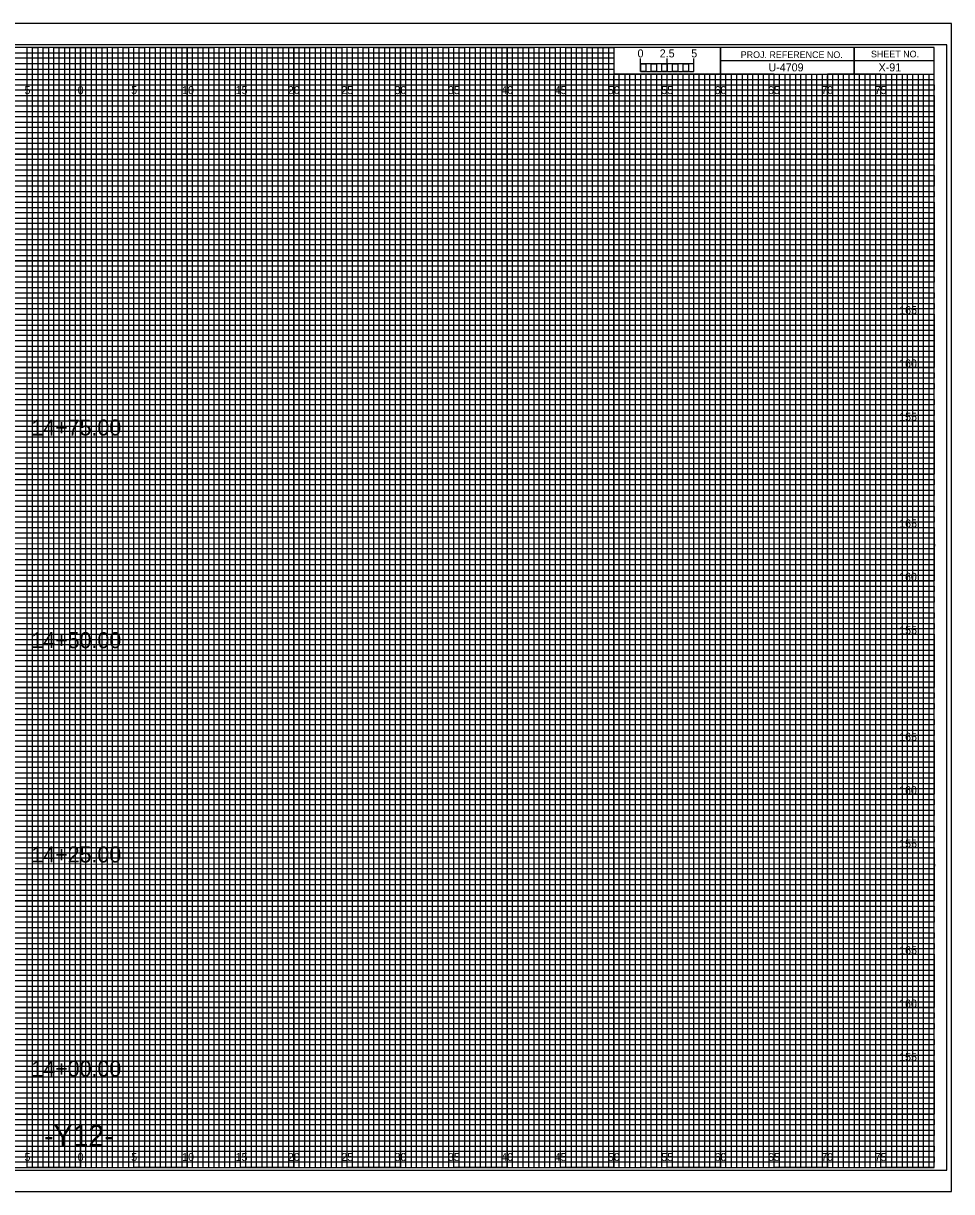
# Model space of a CAD drawing. Extents: x -7 to 162, y 328 to 437.
# Drawn here: x 74.6 to 161.7, y 327.7 to 437.2 of the extents above; entities that cross this region are included whole.
import ezdxf

# ---------------------------------------------------------------- set-up
doc = ezdxf.new("R2010")
doc.units = 0
for name, color, linetype in [('Exist Cross Section Cell', 7, 'Continuous'), ('Exist XS Center Line Elevation Label', 7, 'Continuous'), ('Exist XS Ground Line', 7, 'Continuous'), ('Prop CMT Conc Surface', 7, 'Continuous'), ('Prop CMT Concrete Structures', 7, 'Continuous'), ('Prop CMT Pvmt Course 1', 7, 'Continuous'), ('Prop CMT Pvmt Course 1 CG', 7, 'Continuous'), ('Prop CMT Pvmt Course 2', 7, 'Continuous'), ('Prop CMT Pvmt Course 3', 7, 'Continuous'), ('Prop CMT Pvmt Surface', 7, 'Continuous'), ('Prop CMT Slope Grass', 7, 'Continuous'), ('Prop CMT Subgrade Earthwork', 7, 'Continuous'), ('Prop XS Finish Grade CurbGutter', 7, 'Continuous'), ('Prop XS Hydro Elevations', 7, 'Continuous'), ('Prop XS SE Text', 7, 'Continuous'), ('Prop XS Side Slope Text', 7, 'Continuous'), ('Scratch_Level_0', 7, 'Continuous')]:
    doc.layers.add(name, color=color, linetype=linetype)

msp = doc.modelspace()

# ---------------------------------------------------------------- linework, layer by layer
at = {"layer": 'Exist XS Center Line Elevation Label'}
for points in [[(72.5, 330), (77.5, 330), (77.5, 435), (82.5, 435), (82.5, 330), (87.5, 330), (87.5, 435), (92.5, 435), (92.5, 330), (97.5, 330), (97.5, 435), (102.5, 435), (102.5, 330), (107.5, 330), (107.5, 435), (112.5, 435), (112.5, 330), (117.5, 330), (117.5, 435), (122.5, 435), (122.5, 330), (127.5, 330), (127.5, 435), (129.97, 435), (130, 435), (130, 432.5), (132.5, 432.5), (132.5, 330), (137.5, 330), (137.5, 432.5), (142.5, 432.5), (142.5, 330), (147.5, 330), (147.5, 432.5), (152.5, 432.5), (152.5, 330), (157.5, 330), (157.5, 432.5)], [(0, 432.5), (137.5, 432.5)], [(0, 422.5), (160, 422.5), (160, 427.5), (0, 427.5)], [(0, 412.5), (160, 412.5), (160, 417.5), (0, 417.5)], [(0, 402.5), (160, 402.5), (160, 407.5), (0, 407.5)], [(0, 392.5), (160, 392.5), (160, 397.5), (0, 397.5)], [(0, 382.5), (160, 382.5), (160, 387.5), (0, 387.5)], [(0, 372.5), (160, 372.5), (160, 377.5), (0, 377.5)], [(0, 362.5), (160, 362.5), (160, 367.5), (0, 367.5)], [(0, 352.5), (160, 352.5), (160, 357.5), (0, 357.5)], [(0, 342.5), (160, 342.5), (160, 347.5), (0, 347.5)], [(0, 332.5), (160, 332.5), (160, 337.5), (0, 337.5)]]:
    msp.add_lwpolyline(points, dxfattribs=at)
at = {"layer": 'Exist XS Ground Line'}
for p, q in [((75, 435), (70, 435)), ((75, 330), (75, 435)), ((85, 435), (80, 435)), ((80, 435), (80, 330)), ((85, 330), (85, 435)), ((95, 435), (90, 435)), ((90, 435), (90, 330)), ((95, 330), (95, 435)), ((105, 435), (100, 435)), ((100, 435), (100, 330)), ((105, 330), (105, 435)), ((115, 435), (110, 435)), ((110, 435), (110, 330)), ((115, 330), (115, 435)), ((125, 435), (120, 435)), ((120, 435), (120, 330)), ((125, 330), (125, 435)), ((130, 435), (130, 330)), ((135, 330), (135, 432.5)), ((145, 432.5), (140, 432.5)), ((140, 432.5), (140, 330)), ((145, 330), (145, 432.5)), ((155, 432.5), (150, 432.5)), ((150, 432.5), (150, 330)), ((155, 330), (155, 432.5)), ((80, 330), (75, 330)), ((90, 330), (85, 330)), ((100, 330), (95, 330)), ((110, 330), (105, 330)), ((120, 330), (115, 330)), ((130, 330), (125, 330)), ((140, 330), (135, 330)), ((150, 330), (145, 330)), ((160, 330), (155, 330)), ((160, 330), (160, 330))]:
    msp.add_line(p, q, dxfattribs=at)
for points in [[(0, 430), (160, 430), (160, 425), (0, 425)], [(0, 420), (160, 420), (160, 415), (0, 415)], [(0, 410), (160, 410), (160, 405), (0, 405)], [(0, 400), (160, 400), (160, 395), (0, 395)], [(0, 390), (160, 390), (160, 385), (0, 385)], [(0, 380), (160, 380), (160, 375), (0, 375)], [(0, 370), (160, 370), (160, 365), (0, 365)], [(0, 360), (160, 360), (160, 355), (0, 355)], [(0, 350), (160, 350), (160, 345), (0, 345)], [(0, 340), (160, 340), (160, 335), (0, 335)]]:
    msp.add_lwpolyline(points, dxfattribs=at)
at = {"layer": 'Prop CMT Conc Surface'}
for p, q in [((75, 330), (75, 435)), ((80, 330), (80, 435)), ((85, 330), (85, 435)), ((90, 330), (90, 435)), ((95, 330), (95, 435)), ((100, 330), (100, 435)), ((105, 330), (105, 435)), ((110, 330), (110, 435)), ((115, 330), (115, 435)), ((120, 330), (120, 435)), ((125, 330), (125, 435)), ((130, 330), (130, 432.34)), ((135, 330), (135, 432.34)), ((140, 330), (140, 432.34)), ((145, 330), (145, 432.34)), ((150, 330), (150, 432.34)), ((155, 330), (155, 432.34)), ((0, 430), (160, 430)), ((0, 425), (160, 425)), ((0, 420), (160, 420)), ((0, 415), (160, 415)), ((0, 410), (160, 410)), ((0, 405), (160, 405)), ((0, 400), (160, 400)), ((0, 395), (160, 395)), ((0, 390), (160, 390)), ((0, 385), (160, 385)), ((0, 380), (160, 380)), ((0, 375), (160, 375)), ((0, 370), (160, 370)), ((0, 365), (160, 365)), ((0, 360), (160, 360)), ((0, 355), (160, 355)), ((0, 350), (160, 350)), ((0, 345), (160, 345)), ((0, 340), (160, 340)), ((0, 335), (160, 335))]:
    msp.add_line(p, q, dxfattribs=at)
at = {"layer": 'Prop CMT Pvmt Course 1'}
for p, q in [((133.5, 432.5), (133, 432.5)), ((133, 432.5), (133, 330)), ((133.5, 330), (133.5, 432.5)), ((134.5, 432.5), (134, 432.5)), ((134, 432.5), (134, 330)), ((134.5, 330), (134.5, 432.5)), ((133, 330), (132.5, 330)), ((134, 330), (133.5, 330))]:
    msp.add_line(p, q, dxfattribs=at)
for points in [[(75, 330), (75.5, 330), (75.5, 435), (76, 435), (76, 330)], [(76, 330), (76.5, 330), (76.5, 435), (77, 435), (77, 330)], [(77.5, 330), (78, 330), (78, 435), (78.5, 435), (78.5, 330)], [(78.5, 330), (79, 330), (79, 435), (79.5, 435), (79.5, 330)], [(80, 330), (80.5, 330), (80.5, 435), (81, 435), (81, 330)], [(81, 330), (81.5, 330), (81.5, 435), (82, 435), (82, 330)], [(82.5, 330), (83, 330), (83, 435), (83.5, 435), (83.5, 330)], [(83.5, 330), (84, 330), (84, 435), (84.5, 435), (84.5, 330)], [(85, 330), (85.5, 330), (85.5, 435), (86, 435), (86, 330)], [(86, 330), (86.5, 330), (86.5, 435), (87, 435), (87, 330)], [(87.5, 330), (88, 330), (88, 435), (88.5, 435), (88.5, 330)], [(88.5, 330), (89, 330), (89, 435), (89.5, 435), (89.5, 330)], [(90, 330), (90.5, 330), (90.5, 435), (91, 435), (91, 330)], [(91, 330), (91.5, 330), (91.5, 435), (92, 435), (92, 330)], [(92.5, 330), (93, 330), (93, 435), (93.5, 435), (93.5, 330)], [(93.5, 330), (94, 330), (94, 435), (94.5, 435), (94.5, 330)], [(95, 330), (95.5, 330), (95.5, 435), (96, 435), (96, 330)], [(96, 330), (96.5, 330), (96.5, 435), (97, 435), (97, 330)], [(97.5, 330), (98, 330), (98, 435), (98.5, 435), (98.5, 330)], [(98.5, 330), (99, 330), (99, 435), (99.5, 435), (99.5, 330)], [(100, 330), (100.5, 330), (100.5, 435), (101, 435), (101, 330)], [(101, 330), (101.5, 330), (101.5, 435), (102, 435), (102, 330)], [(102.5, 330), (103, 330), (103, 435), (103.5, 435), (103.5, 330)], [(103.5, 330), (104, 330), (104, 435), (104.5, 435), (104.5, 330)], [(105, 330), (105.5, 330), (105.5, 435), (106, 435), (106, 330)], [(106, 330), (106.5, 330), (106.5, 435), (107, 435), (107, 330)], [(107.5, 330), (108, 330), (108, 435), (108.5, 435), (108.5, 330)], [(108.5, 330), (109, 330), (109, 435), (109.5, 435), (109.5, 330)], [(110, 330), (110.5, 330), (110.5, 435), (111, 435), (111, 330)], [(111, 330), (111.5, 330), (111.5, 435), (112, 435), (112, 330)], [(112.5, 330), (113, 330), (113, 435), (113.5, 435), (113.5, 330)], [(113.5, 330), (114, 330), (114, 435), (114.5, 435), (114.5, 330)], [(115, 330), (115.5, 330), (115.5, 435), (116, 435), (116, 330)], [(116, 330), (116.5, 330), (116.5, 435), (117, 435), (117, 330)], [(117.5, 330), (118, 330), (118, 435), (118.5, 435), (118.5, 330)], [(118.5, 330), (119, 330), (119, 435), (119.5, 435), (119.5, 330)], [(120, 330), (120.5, 330), (120.5, 435), (121, 435), (121, 330)], [(121, 330), (121.5, 330), (121.5, 435), (122, 435), (122, 330)], [(122.5, 330), (123, 330), (123, 435), (123.5, 435), (123.5, 330)], [(123.5, 330), (124, 330), (124, 435), (124.5, 435), (124.5, 330)], [(125, 330), (125.5, 330), (125.5, 435), (126, 435), (126, 330)], [(126, 330), (126.5, 330), (126.5, 435), (127, 435), (127, 330)], [(127.5, 330), (128, 330), (128, 435), (128.5, 435), (128.5, 330)], [(128.5, 330), (129, 330), (129, 435), (129.5, 435), (129.5, 330)], [(130, 330), (130.5, 330), (130.5, 432.5), (131.01, 432.5), (131.01, 330)], [(131, 330), (131.5, 330), (131.5, 432.5), (132, 432.5), (132, 330)], [(135, 330), (135.49, 330), (135.49, 432.5), (136, 432.5), (136, 330)], [(136, 330), (136.5, 330), (136.5, 432.5), (137.03, 432.5), (137.03, 330)], [(137.5, 330), (138, 330), (138, 432.5), (138.5, 432.5), (138.5, 330)], [(138.5, 330), (139, 330), (139, 432.5), (139.5, 432.5), (139.5, 330)], [(140, 330), (140.5, 330), (140.5, 432.5), (141, 432.5), (141, 330)], [(141, 330), (141.5, 330), (141.5, 432.5), (142, 432.5), (142, 330)], [(142.5, 330), (143, 330), (143, 432.5), (143.5, 432.5), (143.5, 330)], [(143.5, 330), (144, 330), (144, 432.5), (144.5, 432.5), (144.5, 330)], [(145, 330), (145.5, 330), (145.5, 432.5), (146, 432.5), (146, 330)], [(146, 330), (146.5, 330), (146.5, 432.5), (147, 432.5), (147, 330)], [(147.5, 330), (148, 330), (148, 432.5), (148.5, 432.5), (148.5, 330)], [(148.5, 330), (149, 330), (149, 432.5), (149.5, 432.5), (149.5, 330)], [(150, 330), (150.5, 330), (150.5, 432.5), (151, 432.5), (151, 330)], [(151, 330), (151.5, 330), (151.5, 432.5), (152, 432.5), (152, 330)], [(152.5, 330), (153, 330), (153, 432.5), (153.5, 432.5), (153.5, 330)], [(153.5, 330), (154, 330), (154, 432.5), (154.5, 432.5), (154.5, 330)], [(155, 330), (155.5, 330), (155.5, 432.5), (156, 432.5), (156, 330)], [(156, 330), (156.5, 330), (156.5, 432.5), (157, 432.5), (157, 330)], [(157.5, 330), (158, 330), (158, 432.5), (158.5, 432.5), (158.5, 330)], [(158.5, 330), (159, 330), (159, 432.5), (159.5, 432.5), (159.5, 330)]]:
    msp.add_lwpolyline(points, dxfattribs=at)
at = {"layer": 'Prop CMT Pvmt Course 1 CG'}
for p, q in [((132.5, 432.75), (132.5, 433.95)), ((132.5, 433.45), (132.5, 433.95)), ((135, 432.75), (135, 433.95)), ((137.5, 432.75), (137.5, 433.95)), ((137.5, 433.45), (137.5, 433.95))]:
    msp.add_line(p, q, dxfattribs=at)
for points in [[(137.5, 433.45), (132.5, 433.45), (132.5, 432.75), (137.5, 432.75)], [(132.5, 433.45), (133, 433.45), (133, 432.75), (132.5, 432.75)], [(133.5, 433.45), (134, 433.45), (134, 432.75), (133.5, 432.75)], [(134.5, 433.45), (135, 433.45), (135, 432.75), (134.5, 432.75)], [(135.5, 433.45), (136, 433.45), (136, 432.75), (135.5, 432.75)], [(136.5, 433.45), (137, 433.45), (137, 432.75), (136.5, 432.75)]]:
    msp.add_lwpolyline(points, close=True, dxfattribs=at)
at = {"layer": 'Prop CMT Pvmt Course 2'}
msp.add_lwpolyline([(-6.7, 327.75), (161.65, 327.75), (161.65, 437.25), (-6.7, 437.25)], close=True, dxfattribs=at)
at = {"layer": 'Prop CMT Pvmt Course 3'}
msp.add_lwpolyline([(-5.4, 329.75), (161.2, 329.75), (161.2, 435.25), (-5.4, 435.25)], close=True, dxfattribs=at)
at = {"layer": 'Prop CMT Slope Grass'}
for p, q in [((161.65, 437.25), (-6.7, 437.25)), ((-6.7, 327.75), (161.65, 327.75))]:
    msp.add_line(p, q, dxfattribs=at)
at = {"layer": 'Prop CMT Subgrade Earthwork'}
for p, q in [((152.5, 435), (152.5, 432.5)), ((152.5, 432.5), (152.5, 435)), ((160, 433.75), (140, 433.75)), ((140, 433.75), (140, 432.5)), ((140, 432.5), (160, 432.5))]:
    msp.add_line(p, q, dxfattribs=at)
for points in [[(160, 435), (0, 435), (0, 330), (160, 330)], [(140, 435), (130, 435), (130, 432.51), (140, 432.51)], [(160, 435), (140, 435), (140, 432.5), (160, 432.5)]]:
    msp.add_lwpolyline(points, close=True, dxfattribs=at)
at = {"layer": 'Scratch_Level_0'}
for p, q in [((0, 434.5), (130, 434.5)), ((130, 433.99), (0, 433.99)), ((130, 434.5), (130, 433.99)), ((0, 433.5), (130, 433.5)), ((130, 432.94), (0, 432.94)), ((130, 433.5), (130, 432.94)), ((0, 432), (160, 432))]:
    msp.add_line(p, q, dxfattribs=at)
for points in [[(0, 431.5), (135, 431.5), (160, 431.5), (160, 431), (0, 431)], [(0, 430.5), (160, 430.5), (160, 429.5), (0, 429.5)], [(0, 429), (160, 429), (160, 428.5), (0, 428.49)], [(0, 428), (160, 428), (160, 427), (0, 427)], [(0, 426.5), (160, 426.5), (160, 426), (0, 426)], [(0, 425.5), (160, 425.5), (160, 424.5), (0, 424.5)], [(0, 424), (160, 424), (160, 423.5), (0, 423.5)], [(0, 423), (160, 423), (160, 422), (0, 422)], [(0, 421.5), (160, 421.5), (160, 421), (0, 421)], [(0, 420.5), (160, 420.5), (160, 419.5), (0, 419.5)], [(0, 419), (160, 419), (160, 418.5), (0, 418.5)], [(0, 418), (160, 418), (160, 416.98), (160, 416.5), (160, 416), (0, 416)], [(0, 417), (160, 417), (160, 416.5), (0, 416.5)], [(0, 415.5), (160, 415.5), (160, 414.5), (0, 414.51)], [(0, 414.51), (160, 414.5), (160, 414), (0, 414)], [(0, 413.5), (160, 413.5), (160, 413), (0, 413)], [(0, 412), (160, 412), (160, 411.5), (0, 411.5)], [(0, 411), (160, 411), (160, 410.5), (0, 410.5)], [(-0.04, 409.44), (160, 409.44), (160, 408.94), (-0.04, 408.94)], [(0, 408.5), (160, 408.5), (160, 408), (0, 408)], [(0, 407), (160, 407), (160, 406.5), (0, 406.5)], [(0, 406), (160, 406), (160, 405.5), (0, 405.5)], [(0, 404.5), (160, 404.5), (160, 404), (0, 404)], [(0, 403.5), (160, 403.5), (160, 403), (0, 403)], [(0, 402), (160, 402), (160, 401.5), (0, 401.5)], [(0, 401), (160, 401), (160, 400.5), (0, 400.5)], [(0, 399.5), (160, 399.5), (160, 398.99), (0, 399)], [(0, 398.5), (160, 398.5), (160, 398), (0, 398)], [(0, 397), (160, 397), (160, 396.5), (0, 396.5)], [(0, 396), (160, 396), (160, 395.5), (0, 395.5)], [(0, 394.5), (160, 394.5), (160, 394), (0, 394)], [(0, 393.5), (160, 393.5), (160, 393), (0, 393)], [(0, 392), (160, 392), (160, 391.5), (0, 391.5)], [(0, 391), (160, 391), (160, 390.5), (0, 390.5)], [(0, 389.5), (160, 389.5), (160, 389), (0, 389)], [(0, 388.5), (160.03, 388.45), (160, 388), (0, 388)], [(0, 387), (160, 387), (160, 386.5), (0, 386.5)], [(0, 386), (160, 386), (160, 385.5), (0, 385.5)], [(0, 384.5), (160, 384.5), (160, 384), (0, 384)], [(0, 383.5), (160, 383.5), (160, 383), (0, 383)], [(0, 382), (160, 382), (160, 381.5), (0, 381.5)], [(0, 381), (160, 381), (160, 380.5), (0, 380.5)], [(0, 379.5), (160, 379.5), (160, 379), (0, 379)], [(0, 378.5), (160, 378.5), (160, 378), (0, 378)], [(0, 377), (160, 377), (160, 376.5), (0, 376.5)], [(0, 376), (160, 376), (160, 375.5), (0, 375.5)], [(0, 374.5), (160, 374.5), (160, 374), (0, 374)], [(0, 373.5), (160, 373.5), (160, 373), (0, 373)], [(0, 372), (160, 372), (160, 371.5), (0, 371.5)], [(0, 371), (160, 371), (160, 370.5), (0, 370.5)], [(0, 369.5), (160, 369.5), (160, 368.99), (0, 369)], [(0, 368.5), (160, 368.5), (160, 368), (0, 368)], [(0, 367), (160, 367), (160, 366.5), (0, 366.5)], [(0, 366), (160, 366), (160, 365.5), (0, 365.5)], [(0, 364.5), (160, 364.5), (160, 364), (0, 364)], [(0, 363.5), (160, 363.5), (160, 363), (0, 363)], [(0, 362), (160, 362), (160, 361.5), (0, 361.5)], [(0, 361), (160, 361), (160, 360.5), (0, 360.5)], [(0, 359.5), (160, 359.5), (160, 359), (0, 359)], [(0, 358.5), (160.03, 358.45), (160, 358), (0, 358)], [(0, 357), (160, 357), (160, 356.5), (0, 356.5)], [(0, 356), (160, 356), (160, 355.5), (0, 355.5)], [(0, 354.5), (160, 354.5), (160, 354), (0, 354)], [(0, 353.5), (160, 353.5), (160, 353), (0, 353)], [(0, 352), (160, 352), (160, 351.5), (0, 351.5)], [(0, 351), (160, 351), (160, 350.5), (0, 350.5)], [(0, 349.5), (160, 349.5), (160, 349), (0, 349)], [(0, 348.5), (160, 348.5), (160, 348), (0, 348)], [(0, 347), (160, 347), (160, 346.5), (0, 346.5)], [(0, 346), (160, 346), (160, 345.5), (0, 345.5)], [(0, 344.5), (160, 344.5), (160, 344), (0, 344)], [(0, 343.5), (160, 343.5), (160, 343), (0, 343)], [(0, 342), (160, 342), (160, 341.5), (0, 341.5)], [(0, 341), (160, 341), (160, 340.5), (0, 340.5)], [(0, 339.5), (160, 339.5), (160, 339), (0, 339)], [(0, 338.5), (160, 338.5), (160, 338), (0, 338)], [(0, 337), (160, 337), (160, 336.5), (0, 336.5)], [(0, 336), (160, 336), (160, 335.5), (0, 335.5)], [(0, 334.5), (160, 334.5), (160, 334), (0, 334)], [(0, 333.5), (160, 333.5), (160, 333), (0, 333)], [(0, 332), (160, 332), (160, 331.5), (0, 331.5)], [(0, 331), (160, 331), (160, 330.5), (0, 330.5)]]:
    msp.add_lwpolyline(points, dxfattribs=at)

# ---------------------------------------------------------------- texts
at = {"layer": 'Exist Cross Section Cell'}
for s, p in [('5', (74.74, 430.62)), ('0', (79.73, 430.62)), ('0', (79.73, 430.62)), ('5', (84.74, 430.62)), ('10', (89.52, 430.62)), ('15', (94.53, 430.62)), ('20', (99.43, 430.62)), ('25', (104.44, 430.62)), ('30', (109.43, 430.62)), ('35', (114.44, 430.62)), ('40', (119.43, 430.62)), ('45', (124.44, 430.62)), ('50', (129.43, 430.62)), ('55', (134.44, 430.62)), ('60', (139.43, 430.62)), ('65', (144.44, 430.62)), ('70', (149.43, 430.62)), ('75', (154.44, 430.62)), ('5', (74.74, 330.62)), ('0', (79.73, 330.62)), ('0', (79.73, 330.62)), ('5', (84.74, 330.62)), ('10', (89.52, 330.62)), ('15', (94.53, 330.62)), ('20', (99.43, 330.62)), ('25', (104.44, 330.62)), ('30', (109.43, 330.62)), ('35', (114.44, 330.62)), ('40', (119.43, 330.62)), ('45', (124.44, 330.62)), ('50', (129.43, 330.62)), ('55', (134.44, 330.62)), ('60', (139.43, 330.62)), ('65', (144.44, 330.62)), ('70', (149.43, 330.62)), ('75', (154.44, 330.62))]:
    msp.add_text(s, height=0.75, dxfattribs=at).set_placement(p)
at = {"layer": 'Prop CMT Concrete Structures'}
for s, p in [('165', (156.73, 410)), ('160', (156.72, 405)), ('155', (156.73, 400)), ('165', (156.73, 390)), ('160', (156.72, 385)), ('155', (156.73, 380)), ('165', (156.73, 370)), ('160', (156.72, 365)), ('155', (156.73, 360)), ('165', (156.73, 350)), ('160', (156.72, 345)), ('155', (156.73, 340))]:
    msp.add_text(s, height=0.75, dxfattribs=at).set_placement(p)
at = {"layer": 'Prop CMT Pvmt Course 1 CG'}
msp.add_text('0', height=0.75, dxfattribs=at).set_placement((132.21, 434.06))
at = {"layer": 'Prop CMT Pvmt Surface'}
for s, p in [('14+75.00', (75.39, 398.62)), ('14+50.00', (75.39, 378.69)), ('14+25.00', (75.39, 358.6)), ('14+00.00', (75.39, 338.53))]:
    msp.add_text(s, height=1.5, dxfattribs=at).set_placement(p)
at = {"layer": 'Prop CMT Subgrade Earthwork'}
for s, p in [('PROJ. REFERENCE NO.', (141.88, 434)), ('SHEET NO.', (154.09, 434.06))]:
    msp.add_text(s, height=0.625, dxfattribs=at).set_placement(p)
at = {"layer": 'Prop XS Finish Grade CurbGutter'}
for s, p in [('2.5', (134.29, 434.06)), ('5', (137.24, 434.06))]:
    msp.add_text(s, height=0.75, dxfattribs=at).set_placement(p)
at = {"layer": 'Prop XS Hydro Elevations'}
msp.add_text('-Y12-', height=2, dxfattribs=at).set_placement((76.57, 332))
at = {"layer": 'Prop XS SE Text'}
msp.add_text('U-4709', height=0.75, dxfattribs=at).set_placement((144.48, 432.75))
at = {"layer": 'Prop XS Side Slope Text'}
msp.add_text('X-91', height=0.75, dxfattribs=at).set_placement((154.8, 432.75))

doc.saveas('drawing.dxf')
